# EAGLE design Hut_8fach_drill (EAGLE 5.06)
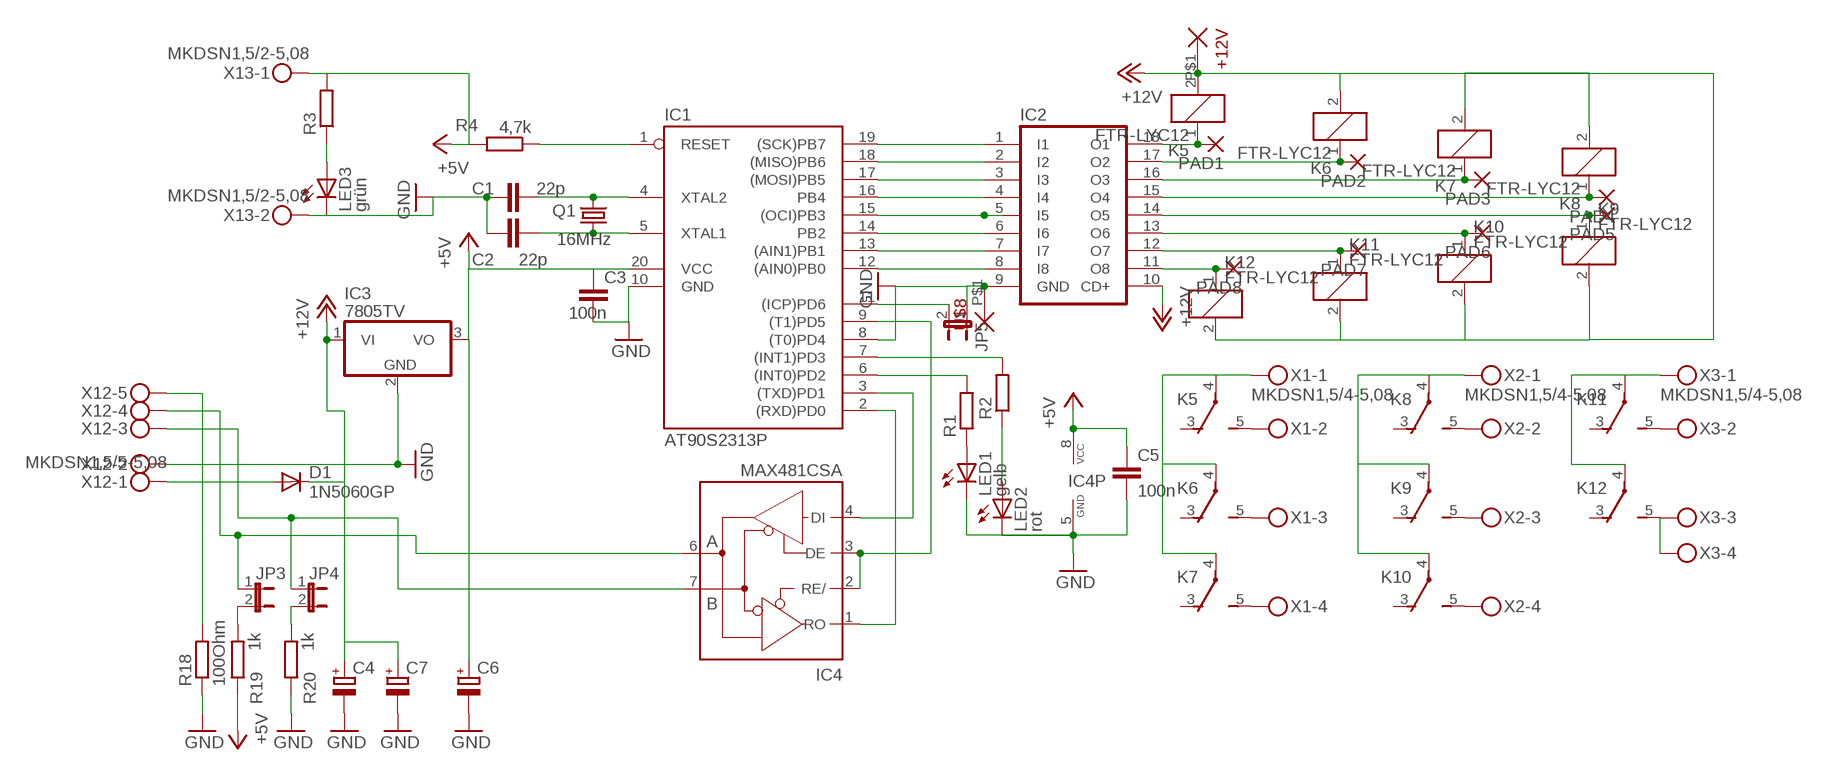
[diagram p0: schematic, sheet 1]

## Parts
+12V  PAD_OVAL  [PAD_OVAL]
C1  22p  C-EUC0603  [C0603]
C2  22p  C-EUC0603  [C0603]
C3  100n  C-EUC0603  [C0603]
C4  CPOL-EUE2.5-7  [E2,5-7]
C5  100n  C-EUC0603  [C0603]
C6  CPOL-EUE2.5-7  [E2,5-7]
C7  CPOL-EUE5-10.5  [E5-10,5]
D1  1N5060GP  [DO15-12]
IC1  AT90S2313P  [DIL20]
IC2  ULN2803A  [DIL18]
IC3  7805TV  [TO220V]
IC4  MAX481CSA  [SO08]
JP3  JP1E  [JP1]
JP4  JP1E  [JP1]
JP5  JP1E  [JP1]
K5  FTR-LYC12  [FTR-LYC]
K6  FTR-LYC12  [FTR-LYC]
K7  FTR-LYC12  [FTR-LYC]
K8  FTR-LYC12  [FTR-LYC]
K9  FTR-LYC12  [FTR-LYC]
K10  FTR-LYC12  [FTR-LYC]
K11  FTR-LYC12  [FTR-LYC]
K12  FTR-LYC12  [FTR-LYC]
LED1  gelb  LED3MM  [LED3MM]
LED2  rot  LED3MM  [LED3MM]
LED3  grün  LED3MM  [LED3MM]
PAD1  2,15/1,0  [2,15/1,0]
PAD2  2,15/1,0  [2,15/1,0]
PAD3  2,15/1,0  [2,15/1,0]
PAD4  2,15/1,0  [2,15/1,0]
PAD5  2,15/1,0  [2,15/1,0]
PAD6  2,15/1,0  [2,15/1,0]
PAD7  2,15/1,0  [2,15/1,0]
PAD8  2,15/1,0  [2,15/1,0]
Q1  16MHz  CRYSTALHC49S  [HC49/S]
R1  R-EU_R1206  [R1206]
R2  R-EU_R1206  [R1206]
R3  R-EU_R1206  [R1206]
R4  4,7k  R-EU_R0603  [R0603]
R18  100Ohm  R-EU_R0603  [R0603]
R19  1k  R-EU_R0603  [R0603]
R20  1k  R-EU_R0603  [R0603]
U$8  PAD_OVAL  [PAD_OVAL]
X1  MKDSN1,5/4-5,08  [MKDSN1,5/4-5,08]
X2  MKDSN1,5/4-5,08  [MKDSN1,5/4-5,08]
X3  MKDSN1,5/4-5,08  [MKDSN1,5/4-5,08]
X12  MKDSN1,5/5-5,08  [MKDSN1,5/5-5,08]
X13  MKDSN1,5/2-5,08  [MKDSN1,5/2-5,08]

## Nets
+5V: C3.1 C5.1 C6.+ IC1.20(VCC) IC3.3(VO) IC4.8(VCC) R3.2 R4.2 R19.1 X13.1
+12V: +12V.P$1 C4.+ C7.+ D1.C IC2.10(CD+) IC3.1(VI) K5.2 K6.2 K7.2 K8.2 K9.2 K10.2 K11.2 K12.2
GND: C1.1 C2.1 C3.2 C4.- C5.2 C6.- C7.- IC1.8((T0)PD4) IC1.10(GND) IC2.9(GND) IC3.2(GND) IC4.5(GND) JP5.1 LED1.K(C) LED2.K(C) LED3.K(C) R18.1 R20.1 U$8.P$1 X12.2 X13.2
N$1: IC1.11((ICP)PD6) JP5.2
N$2: IC1.19((SCK)PB7) IC2.1(I1)
N$3: IC4.6(A) JP3.1 X12.4
N$4: IC4.7(B) JP4.1 X12.3
N$5: R18.2 X12.5
N$6: JP3.2 R19.2
N$7: JP4.2 R20.2
N$8: LED3.A R3.1
N$9: IC1.18((MISO)PB6) IC2.2(I2)
N$10: IC1.1(RESET) R4.1
N$11: C2.2 IC1.5(XTAL1) Q1.1
N$12: C1.2 IC1.4(XTAL2) Q1.2
N$13: IC1.17((MOSI)PB5) IC2.3(I3)
N$14: IC1.3((TXD)PD1) IC4.4(DI)
N$15: IC1.9((T1)PD5) IC4.2(RE/) IC4.3(DE)
N$16: IC1.2((RXD)PD0) IC4.1(RO)
N$17: LED1.A R1.1
N$18: LED2.A R2.1
N$19: IC1.6((INT0)PD2) R1.2
N$20: IC1.7((INT1)PD3) R2.2
N$21: IC1.16(PB4) IC2.4(I4)
N$22: IC1.15((OCI)PB3) IC2.5(I5)
N$23: IC1.14(PB2) IC2.6(I6)
N$24: IC1.13((AIN1)PB1) IC2.7(I7)
N$25: IC1.12((AIN0)PB0) IC2.8(I8)
N$26: IC2.18(O1) K5.1 PAD1.1(P)
N$27: IC2.17(O2) K6.1 PAD2.1(P)
N$28: IC2.16(O3) K7.1 PAD3.1(P)
N$29: IC2.15(O4) K8.1 PAD4.1(P)
N$30: D1.A X12.1
N$32: IC2.14(O5) K9.1 PAD5.1(P)
N$33: IC2.13(O6) K10.1 PAD6.1(P)
N$36: IC2.12(O7) K11.1 PAD7.1(P)
N$39: IC2.11(O8) K12.1 PAD8.1(P)
N$43: K7.5(-1:S) X1.4
N$44: K6.5(-1:S) X1.3
N$45: K5.5(-1:S) X1.2
N$46: K8.5(-1:S) X2.2
N$47: K9.5(-1:S) X2.3
N$48: K10.5(-1:S) X2.4
N$49: K11.5(-1:S) X3.2
N$50: K12.5(-1:S) X3.3 X3.4
N$51: K5.4(-1:P) K6.4(-1:P) K7.4(-1:P) X1.1
N$52: K8.4(-1:P) K9.4(-1:P) K10.4(-1:P) X2.1
N$53: K11.4(-1:P) K12.4(-1:P) X3.1
Unconnected: K5.3(-1:O) K6.3(-1:O) K7.3(-1:O) K8.3(-1:O) K9.3(-1:O) K10.3(-1:O) K11.3(-1:O) K12.3(-1:O)

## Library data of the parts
+12V U$8 = Pad_Oval:PAD_OVAL
C1-C3 C5 = rcl:C-EU: CAPACITOR, European symbol
C4 C6 C7 = rcl:CPOL-EU: POLARIZED CAPACITOR, European symbol
D1 = diode:1N5060GP: DIODE
IC1 = atmel:AT90S2313: MICROCONTROLLER 2 Kbytes FLASH 128 bytes SRAM 128 bytes EEPROM UART
IC2 = uln-udn:ULN2803A: DRIVER ARRAY
IC3 = linear:78*: Positive VOLTAGE REGULATOR Source: http://cache.national.com/ds/LM/LM78L05.pdf http://www.fairchildsemi.com/ds/LM/LM7805.pdf
IC4 = maxim:MAX481CSA: RS485 TRANSEIVER
JP3-JP5 = jumper:JP1E: JUMPER
K5-K12 = relay:FTR-LYC: Schmales Netzrelais NETZRELAIS FTR-LYCA024V 1XUM 6A/250VAC Distributor: Conrad electronic Bestell Nr.: 504382 - 62 Source: http://www2.produktinfo.conrad.com/datenblaetter/500000-524999/504382-da-01-de-NETZRELAIS_FTR-LYCA024V_1XUM_6A_250VAC.pdf
LED1-LED3 = led:LED: LED
PAD1-PAD8 = wirepad:2,15/1,0: THROUGH-HOLE PAD
Q1 = crystal:CRYSTAL: CRYSTAL
R1-R4 R18-R20 = rcl:R-EU_: RESISTOR, European symbol
X1-X3 = con-phoenix-508:MKDSN1,5/4-5,08: MKDSN 1,5/ 4-5,08 Printklemme Nennstrom: 13,5 A Nennspannung: 250 V Rastermaß: 5,08 mm Polzahl: 4 Anschlussart: Schraubanschluss Montage: Löten Anschlussrichtung Leiter/Platine: 0 ° Artikelnummer: 1729144 Source: http://eshop.phoenixcontact.com .. 1729144.pdf
X12 = con-phoenix-508:MKDSN1,5/5-5,08: MKDSN 1,5/ 5-5,08 Printklemme Nennstrom: 13,5 A Nennspannung: 250 V Rastermaß: 5,08 mm Polzahl: 5 Anschlussart: Schraubanschluss Montage: Löten Anschlussrichtung Leiter/Platine: 0 ° Artikelnummer: 1729157 Source: http://eshop.phoenixcontact.com .. 1729157.pdf
X13 = con-phoenix-508:MKDSN1,5/2-5,08: MKDSN 1,5/ 2-5,08 Printklemme

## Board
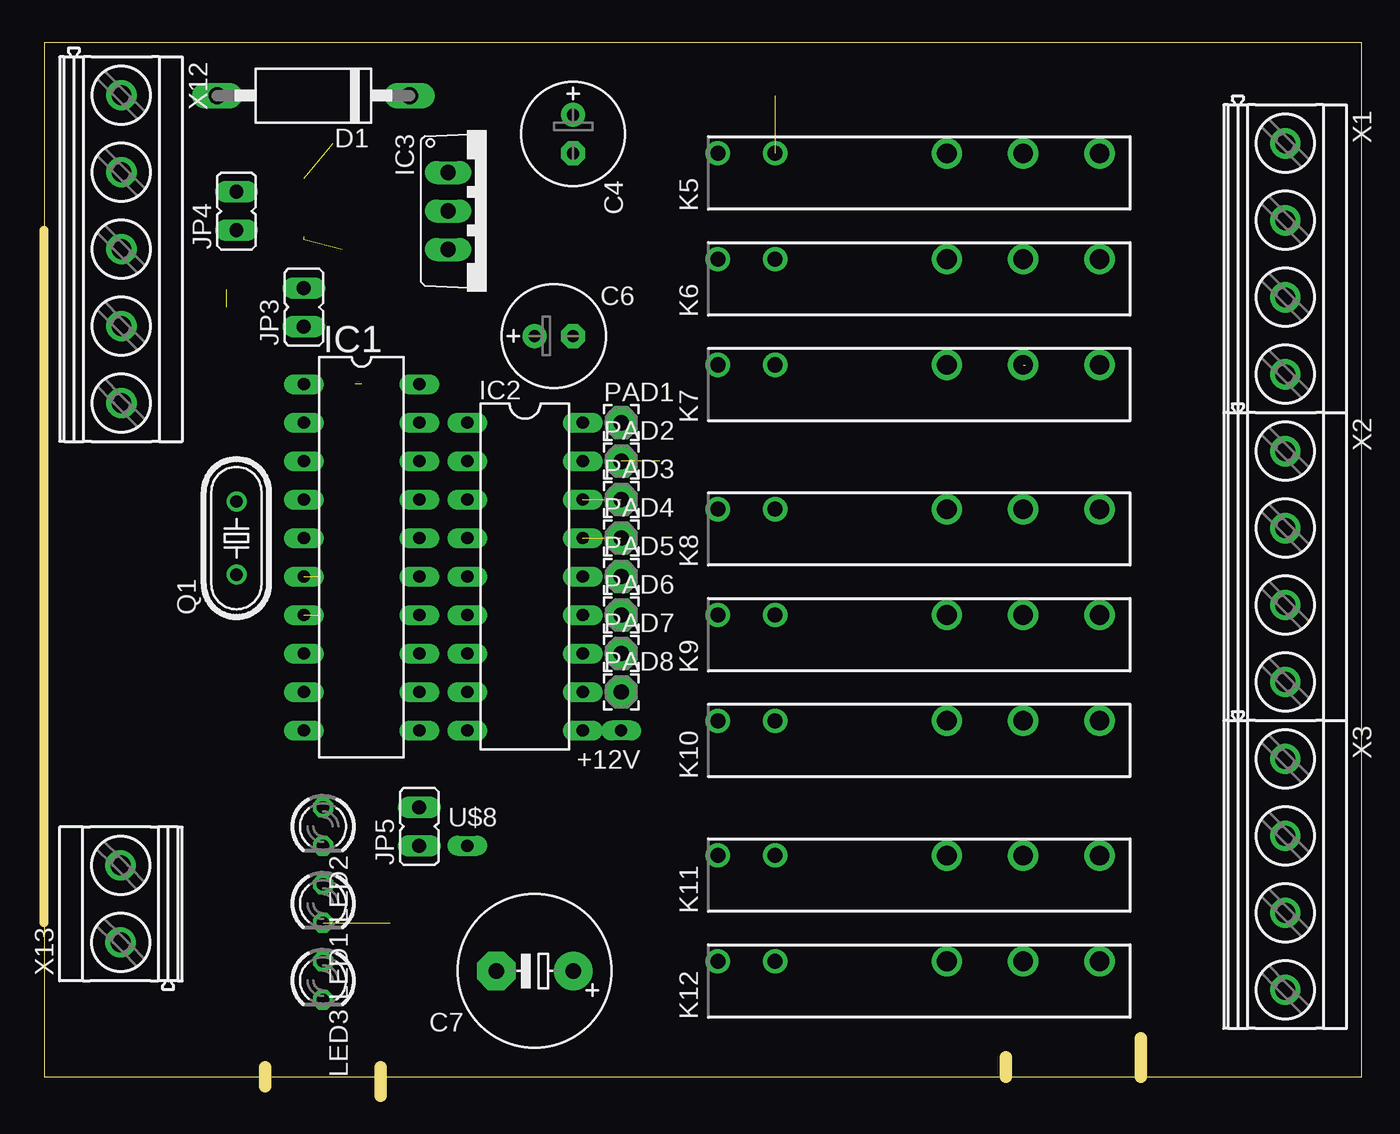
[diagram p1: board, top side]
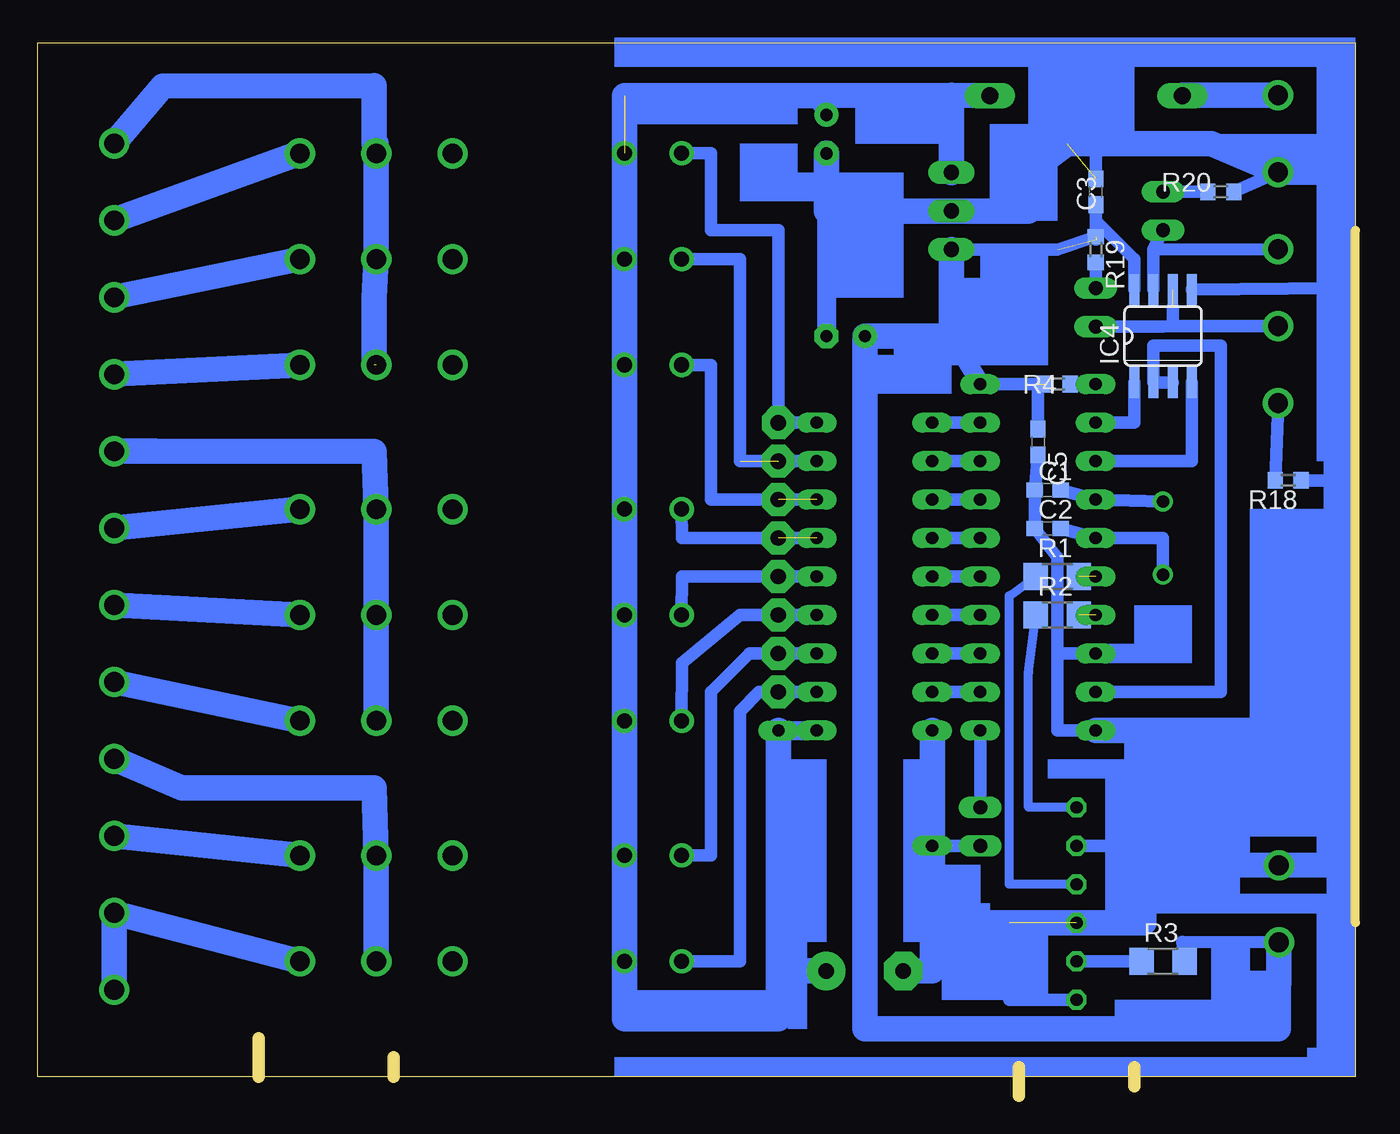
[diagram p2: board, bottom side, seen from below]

Size 86.97 x 69.52 mm. Coordinates in mm from the lower left corner, seen from the top.
Outline: 14.61,1.27 0,1.27 0,11.43 0,57.15 0,69.52 86.97,69.52 86.97,1.27 72.39,1.27
Outline: 14.61,1.27 63.5,1.27
Outline: 63.5,1.27 72.39,1.27
Outline: 14.61,1.27 14.61,1.91
Outline: 14.61,1.27 14.61,0.64
Outline: 22.23,0 22.23,1.91
Outline: 72.39,1.27 72.39,3.81
Outline: 63.5,1.27 63.5,2.54
Copper layers (1*16): Top 0.035mm / dielectric 1.5mm / Bottom 0.035mm
Design rules "default": minimum track width 10mil, minimum drill 24mil, track to track 8mil, track to pad 8mil, pad to pad 8mil, via to via 8mil, smd to smd 8mil, copper to edge 40mil, drill to drill 8mil, minimum pad ring 10mil, minimum via ring 8mil, stop-mask expansion 4mil, vias tented up to drill 0mil, thermal gap 10mil

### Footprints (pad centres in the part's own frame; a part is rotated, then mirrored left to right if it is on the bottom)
PAD_OVAL = drill 0.8 long: P$1 0,0
C0603 = smd 1.1 x 1: 1 -0.85,0; 2 0.85,0
E2,5-7 = drill 0.813 pad 1.6 round: + -1.27,0 | drill 0.813 pad 1.6 octagon: - 1.27,0
E5-10,5 = drill 1.016 pad 2.54 round: + -2.54,0 | drill 1.016 pad 2.54 octagon: - 2.54,0
DO15-12 = drill 1.118 long: A 6.35,0; C -6.35,0
DIL20 = drill 0.813 long: 1 -11.43,-3.81; 2 -8.89,-3.81; 3 -6.35,-3.81; 4 -3.81,-3.81; 5 -1.27,-3.81; 6 1.27,-3.81; 7 3.81,-3.81; 8 6.35,-3.81; 9 8.89,-3.81; 10 11.43,-3.81; 11 11.43,3.81; 12 8.89,3.81; 13 6.35,3.81; 14 3.81,3.81; 15 1.27,3.81; 16 -1.27,3.81; 17 -3.81,3.81; 18 -6.35,3.81; 19 -8.89,3.81; 20 -11.43,3.81
DIL18 = drill 0.813 long: 1 -10.16,-3.81; 2 -7.62,-3.81; 3 -5.08,-3.81; 4 -2.54,-3.81; 5 0,-3.81; 6 2.54,-3.81; 7 5.08,-3.81; 8 7.62,-3.81; 9 10.16,-3.81; 10 10.16,3.81; 11 7.62,3.81; 12 5.08,3.81; 13 2.54,3.81; 14 0,3.81; 15 -2.54,3.81; 16 -5.08,3.81; 17 -7.62,3.81; 18 -10.16,3.81
TO220V = drill 1.016 long: 1 -2.54,-2.54; 2 0,-2.54; 3 2.54,-2.54
SO08 = smd 0.66 x 2.032: 1 -1.905,-3.073; 2 -0.635,-3.073; 3 0.635,-3.073; 4 1.905,-3.073; 5 1.905,3.073; 6 0.635,3.073; 7 -0.635,3.073; 8 -1.905,3.073
JP1 = drill 0.914 long: 1 0,-1.27; 2 0,1.27
FTR-LYC = drill 1 pad 1.6 round: 1 -3.78,0; 2 0,0 | drill 1.3 pad 2 round: 3 11.34,0; 4 16.38,0; 5 21.42,0
LED3MM = drill 0.813 octagon: A -1.27,0; K 1.27,0
2,15/1,0 = drill 1.016 pad 2.159 octagon: 1 0,0
HC49/S = drill 0.813 round: 1 -2.413,0; 2 2.413,0
R1206 = smd 1.6 x 1.803: 1 -1.422,0; 2 1.422,0
R0603 = smd 1 x 1.1: 1 -0.85,0; 2 0.85,0
MKDSN1,5/4-5,08 = drill 1.3 pad 2 round: 1 -7.641,0.025; 2 -2.561,0.025; 3 2.519,0.025; 4 7.599,0.025
MKDSN1,5/5-5,08 = drill 1.3 pad 2 round: 1 -10.181,0.025; 2 -5.101,0.025; 3 -0.021,0.025; 4 5.059,0.025; 5 10.139,0.025
MKDSN1,5/2-5,08 = drill 1.3 pad 2 round: 1 -2.561,0.025; 2 2.519,0.025

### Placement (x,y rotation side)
+12V  38.1,24.13 180 top
C1  20.32,40.01 0 bottom
C2  20.32,37.47 0 bottom
C3  17.14,59.69 90 bottom
C4  34.92,63.5 270 top
C5  20.95,43.18 270 bottom
C6  33.66,50.17 0 top
C7  32.38,8.26 180 top
D1  17.78,66.04 180 top
IC1  20.95,35.56 270 top
IC2  31.75,34.29 270 top
IC3  29.21,58.42 270 top
IC4  12.7,50.17 0 bottom
JP3  17.14,52.07 0 top
JP4  12.7,58.42 0 top
JP5  24.77,17.78 0 top
K5  48.26,62.23 0 top
K6  48.26,55.25 0 top
K7  48.26,48.26 0 top
K8  48.26,38.74 0 top
K9  48.26,31.75 0 top
K10  48.26,24.77 0 top
K11  48.26,15.88 0 top
K12  48.26,8.89 0 top
LED1  18.41,12.7 270 top
LED2  18.41,17.78 270 top
LED3  18.41,7.62 270 top
PAD1  38.1,44.45 0 top
PAD2  38.1,41.91 0 top
PAD3  38.1,39.37 0 top
PAD4  38.1,36.83 0 top
PAD5  38.1,34.29 0 top
PAD6  38.1,31.75 0 top
PAD7  38.1,29.21 0 top
PAD8  38.1,26.67 0 top
Q1  12.7,36.83 90 top
R1  19.68,34.29 0 bottom
R2  19.68,31.75 0 bottom
R3  12.7,8.89 0 bottom
R4  19.68,46.99 180 bottom
R18  4.45,40.64 180 bottom
R19  17.14,55.88 270 bottom
R20  8.89,59.69 180 bottom
U$8  27.94,16.51 0 top
X1  81.92,55.25 270 top
X2  81.92,34.93 270 top
X3  81.92,14.61 270 top
X12  5.08,55.88 270 top
X13  5.08,12.7 90 top

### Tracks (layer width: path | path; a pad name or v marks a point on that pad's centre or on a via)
+5V  (3 unrouted)
  Bottom 0.813: IC4.8 14.61,55.25 17.14,57.79 | 17.14,56.52 17.14,57.79 | R19.1 19.68,55.88 IC3.3 | IC1.20 20.95,46.99 C5.1 | 17.14,57.79 C3.1 | X13.1 11.43,10.16 R3.2
  Bottom 1.27: 26.67,50.17 IC1.20
  Bottom 1.676: IC3.3 26.67,50.17 C6.+ 32.38,4.45 5.08,4.45 X13.1
+12V  (1 unrouted)
  Bottom 1.27: +12V.P$1 IC2.10 | 35.56,66.04 C4.+
  Bottom 1.676: 26.67,66.05 35.56,66.04 48.26,66.04 K6.2 K7.2 K8.2 K9.2 K10.2 K11.2 48.26,9.53 | 26.67,66.05 IC3.1 | 48.26,9.53 K12.2 | 48.26,9.53 48.26,5.08 38.1,5.08 38.1,8.26 | 38.1,8.26 +12V.P$1 | C7.+ 38.1,8.26 | D1.C 24.77,66.04 26.67,66.05
GND  (2 unrouted)
  Bottom 0.813: X12.2 R20.1 | 17.14,62.87 C3.2 | C5.2 C1.1 C2.1 19.68,35.56 19.68,29.21 | 19.68,29.21 IC1.8 | 1.27,40.64 R18.1 | 1.27,53.34 IC4.5 | 19.68,29.21 19.68,24.13 IC1.10 | LED2.K 13.97,16.51 13.97,15.24 | LED3.K 22.86,6.35 22.86,11.43 | JP5.1 U$8.P$1
  Bottom 1.27: 34.92,58.42 C6.-
  Bottom 1.676: 26.04,58.42 34.92,58.42 C4.- | 26.04,58.42 IC3.2 | 1.27,24.13 1.27,40.64 1.27,53.34 1.27,60.96 X12.2 9.53,62.87 17.14,62.87 19.05,62.87 21.59,60.96 21.59,58.42 26.04,58.42 | 1.27,24.13 IC1.10 | 1.27,24.13 1.27,15.24 X13.2 13.97,15.24 13.97,11.43 22.86,11.43 27.94,11.43 | IC2.9 U$8.P$1 27.94,11.43 | C7.- 27.94,8.26 27.94,11.43
N$1
  Bottom 0.813: JP5.2 IC1.11
N$2
  Bottom 0.813: IC1.19 IC2.1
N$3  (1 unrouted)
  Bottom 0.406: X12.4 5.08,50.82
  Bottom 0.813: X12.4 12.06,50.82 | 12.06,50.82 12.06,52.07 | 12.06,50.82 12.7,50.8 JP3.1
N$4
  Bottom 0.813: 13.34,55.88 IC4.7 | 13.34,55.88 JP4.1 | X12.3 13.34,55.88
N$5
  Bottom 0.813: R18.2 X12.5
N$6
  Bottom 0.813: JP3.2 R19.2
N$7
  Bottom 0.813: R20.2 JP4.2
N$8
  Bottom 0.813: R3.1 LED3.A
N$9
  Bottom 0.813: IC1.18 IC2.2
N$10
  Bottom 0.813: IC1.1 R4.1
N$11
  Bottom 0.813: Q1.1 12.7,36.83 IC1.5 C2.2
N$12
  Bottom 0.813: Q1.2 IC1.4 C1.2
N$13
  Bottom 0.813: IC1.17 IC2.3
N$14
  Bottom 0.813: IC4.4 10.79,41.91 IC1.3
N$15
  Bottom 0.813: IC4.3 IC4.2 13.34,49.53 8.89,49.53 8.89,26.67 IC1.9
N$16
  Bottom 0.813: IC4.1 14.61,44.45 IC1.2
N$17
  Bottom 0.61: R1.1 22.86,33.02 22.86,13.97 LED1.A
N$18
  Bottom 0.61: R2.1 21.59,27.94 21.59,19.05 LED2.A
N$19  (1 unrouted)
N$20  (1 unrouted)
N$21
  Bottom 0.813: IC1.16 IC2.4
N$22
  Bottom 0.813: IC1.15 IC2.5
N$23
  Bottom 0.813: IC1.14 IC2.6
N$24
  Bottom 0.813: IC1.13 IC2.7
N$25
  Bottom 0.813: IC1.12 IC2.8
N$26
  Bottom 0.813: IC2.18 PAD1.1 38.1,57.15 42.55,57.15 42.55,62.23 K5.1
N$27  (1 unrouted)
  Bottom 0.813: IC2.17 40.64,41.91 40.64,55.25 K6.1
N$28  (1 unrouted)
  Bottom 0.813: IC2.16 42.55,39.37 42.55,48.26 K7.1
N$29  (1 unrouted)
  Bottom 0.813: IC2.15 44.45,36.83 K8.1
N$30
  Bottom 1.676: X12.1 11.43,66.06 D1.A
N$32
  Bottom 0.813: IC2.14 PAD5.1 44.45,34.29 K9.1
N$33
  Bottom 0.813: IC2.13 PAD6.1 40.64,31.75 44.45,28.57 K10.1
N$36
  Bottom 0.813: IC2.12 PAD7.1 40.01,29.21 42.55,26.67 42.55,15.88 K11.1
N$39
  Bottom 0.813: K12.1 40.64,8.89 40.64,25.4 39.37,26.67 PAD8.1 IC2.11
N$43
  Bottom 1.676: K7.5 X1.4
N$44
  Bottom 1.676: K6.5 X1.3
N$45
  Bottom 1.676: K5.5 X1.2
N$46
  Bottom 1.676: K8.5 X2.2
N$47
  Bottom 1.676: K9.5 X2.3
N$48
  Bottom 1.676: K10.5 X2.4
N$49
  Bottom 1.676: K11.5 X3.2
N$50
  Bottom 1.676: K12.5 X3.3 X3.4
N$51  (1 unrouted)
  Bottom 1.676: 64.77,48.26 64.77,52.71 K6.4 K5.4 64.64,62.87 64.77,62.87 64.77,66.7 78.74,66.67 X1.1
N$52
  Bottom 1.676: X2.1 79.22,42.59 64.77,42.55 K8.4 K9.4 K10.4
N$53
  Bottom 1.676: K12.4 K11.4 64.77,20.32 77.47,20.32 X3.1
(copper drawn outside any net)
  shapes: Bottom area x56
